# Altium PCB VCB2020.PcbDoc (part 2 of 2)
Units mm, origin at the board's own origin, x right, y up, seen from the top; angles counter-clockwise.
Board outline 146 x 101 mm, 2 copper layers (Top Layer, Bottom Layer); 144 components, 94 nets, 477 pads, 404 vias.
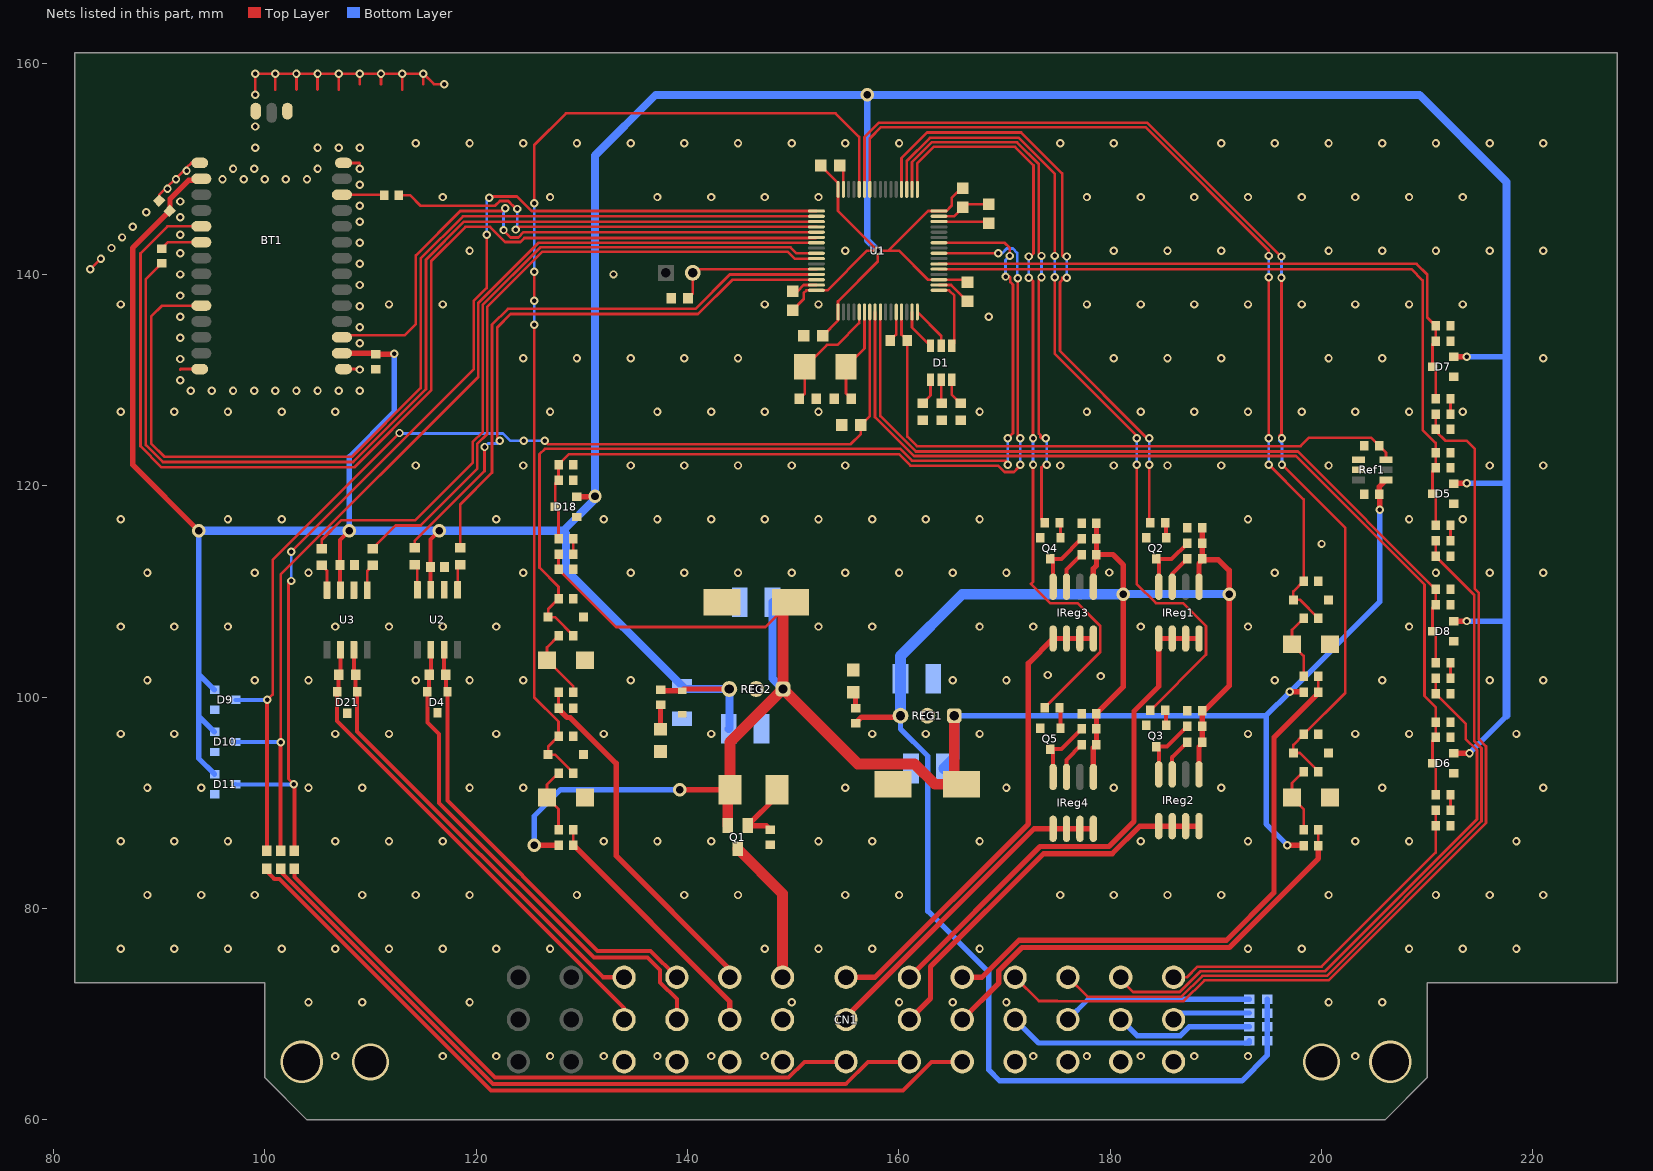
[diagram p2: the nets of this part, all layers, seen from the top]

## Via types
v1: diameter 0.787, hole 0.432, Top Layer to Bottom Layer, 391 vias
v2: diameter 1.27, hole 0.711, Top Layer to Bottom Layer, 9 vias
v3: diameter 3.5, hole 3, Top Layer to Bottom Layer, 2 vias
v4: diameter 4, hole 3.5, Top Layer to Bottom Layer, 2 vias

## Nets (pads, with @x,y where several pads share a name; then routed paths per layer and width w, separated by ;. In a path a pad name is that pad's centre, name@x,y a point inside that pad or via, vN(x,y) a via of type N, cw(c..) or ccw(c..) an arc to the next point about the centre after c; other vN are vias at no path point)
3v3: BT1.2 BT1.16 C5.2 C6.2 C7.2 C8.2 C9.2 C18.2 C19.2 C24.2 C28.2 C29.2 D3.1 D5.2 D6.2 D7.2 D8.2 D9.2 D10.2 D11.2 D18.2 R7.1 R8.2 REG2.3 U1.1 U1.19 U1.32 U1.48 U1.64 U2.3 U3.3 | length 440.5
  Top Layer w0.254: C9.2@149.946,136.6 151,137.654 151,138.25 151.25,138.5 U1.64@152.2,138.5 153.242,138.5 156.992,142.25 v1(158,142.25) ; C6.2@152.6,150.304 154.25,148.654 U1.48@154.25,148.05 154.25,146 v1(158,142.25) ; C5.2@152.8,134.196 154.25,135.646 U1.1@154.25,136.45 154.25,137.45 158,141.2 v1(158,142.25) ; C7.2@166.054,148.15 165.9,148.15 165,147.25 165,146.5 164.5,146 U1.32@163.8,146 162.758,146 159.008,142.25 ; C8.2@166.5,139.25 166.25,139.5 U1.19@163.8,139.5 162.758,139.5 160.008,142.25 159.008,142.25 ; v1(158,142.25) 159.008,142.25
  Top Layer w0.381: U3.3@107.165,110.134 107.125,110.174 C24.2@107.125,112.513 107.125,114.875 v2(108,115.75) ; U2.3@115.71,110.15 115.67,110.19 C19.2@115.67,112.329 115.67,114.92 v2(116.5,115.75)
  Top Layer w0.508: C28.2@90.995,146.005 91.038,146.048 91.038,147.145 92.792,148.9 93.85,148.9 BT1.2@94,149.05 ; C28.2@91,146 87.5,142.5 87.5,122 v2(93.75,115.75) ; BT1.16@107.3,132.55 110.4,132.55 C29.2@110.5,132.45 112.2,132.45 v1(112.25,132.5) ; D18.2@129.5,118.95 131.2,118.95 v2(131.25,119) ; R7.1@137.45,100.7 137.535,100.615 D3.1@139.5,100.615 139.655,100.77 REG2.3@143.96,100.77 ; D6.2@212.5,94.7 v1(214,94.7) ; D8.2@212.5,107.2 v1(213.75,107.2) ; D5.2@212.5,120.2 212.55,120.25 v1(213.75,120.25) ; D7.2@212.5,132.2 v1(213.75,132.2)
  Bottom Layer w0.508: v2(93.75,115.75) 93.75,102.2 ; D11.2@95.25,92.721 93.75,94.221 93.75,98.211 ; D10.2@95.25,96.711 93.75,98.211 ; D9.2@95.25,100.7 93.75,102.2 ; v2(108,115.75) 108,122.75 112.25,127 v1(112.25,132.5) ; v1(213.75,107.2) 217.45,107.2 217.5,107.25 ; v1(213.75,120.25) 217.25,120.25 217.5,120.5 ; v1(213.75,132.2) 217.45,132.2 217.5,132.25 ; v1(214,94.7) 217.5,98.2 217.5,98.25 ; 93.75,98.211 93.75,102.2
  Bottom Layer w0.635: v2(157,157) 157,143.25 v1(158,142.25)
  Bottom Layer w0.762: v2(93.75,115.75) v2(108,115.75) v2(116.5,115.75) 128.25,115.75 ; C18.2@143.9,97 143.96,97.06 REG2.3@143.96,100.77 ; REG2.3@144.23,100.77 REG2.3@143.96,100.77 ; 217.5,98.25 217.5,107.25 217.5,120.5 217.5,132.25 217.5,148.75 209.25,157 v2(157,157) 137,157 131.25,151.25 v2(131.25,119) 131.25,118.75 128.25,115.75 ; 128.25,115.75 128.5,115.5 128.5,112.05 R8.2@139.5,101.05 139.78,100.77 REG2.3@143.96,100.77
3v3ref: C3.2 C11.2 Ref1.6 U1.13 | length 59.3
  Top Layer w0.254: U1.13@160.25,136.45 160.25,134.3 C3.2@160.8,133.75 160.8,124.671 161.721,123.75 198,123.75 198.809,124.559 204.695,124.559 C11.2@205.45,123.804 206.1,123.154 Ref1.6@206.1,122.45
5v: C14.2 C34.2 C35.2 C36.2 C37.2 F1.1 F2.1 F3.1 F4.1 IReg1.1 IReg2.1 IReg3.1 IReg4.1 R6.1 R47.1 R48.1 R50.1 R51.1 R53.1 R54.1 R56.1 R57.1 REG1.3 | length 172.5
  Top Layer w0.508: R6.1@155.904,97.55 156.472,98.118 160.16,98.118 REG1.3@160.16,98.25 ; IReg4.1@178.405,92.45 178.405,95.205 R56.1@178.7,95.5 R57.1@178.7,97 C37.2@178.7,98.454 181.25,101.004 v2(181.25,109.75) 181.25,112.5 180.25,113.5 R53.1@178.7,113.5 ; IReg3.1@178.405,110.45 178.405,112.155 178.7,112.45 R53.1@178.7,113.5 ; C36.2@178.7,116.454 R54.1@178.7,115 R53.1@178.7,113.5 ; IReg2.1@188.405,92.95 188.405,95.309 188.7,95.604 188.7,97.059 R51.1@188.7,97.25 188.7,98.513 191.25,101.063 v2(191.25,109.75) 191.25,112 190.25,113 188.75,113 188.405,112.655 IReg1.1@188.405,110.45 ; R47.1@188.7,113.5 C34.2@188.7,116.013
  Bottom Layer w0.508: REG1.3@160.16,98.25 160.16,97.001 162.75,94.411 162.75,79.75 168.5,74 168.5,64.75 169.55,63.7 192.45,63.7 194.85,66.1 F4.1@194.85,67.5 F3.1@194.85,68.807 F1.1@194.85,70.113 F2.1@194.85,71.42
  Bottom Layer w0.762: v2(181.25,109.75) v2(191.25,109.75)
  Bottom Layer w1.016: REG1.3@160.16,98.25 160.16,101.74 C14.2@160.15,101.75 160.15,103.9 166,109.75 v2(181.25,109.75)
"APPS 1 5V": CN1.1 R16.1 R18.2 | length 33.7
  Top Layer w0.254: CN1.1@186,73.5 187.25,73.5 188.25,74.5 200,74.5 210.8,85.3 R18.2@210.8,87.837 R16.1@210.8,89.291
"APPS 1 Pwr": CN1.2 F1.2 | length 7.4
  Bottom Layer w0.508: CN1.2@186,69.5 186.613,70.113 F1.2@193.15,70.113
"APPS 2 5V": CN1.7 R12.1 R14.2 | length 75.1
  Top Layer w0.254: CN1.7@176,73.5 177.837,71.663 186.761,71.663 188.734,73.636 200.497,73.636 215.13,88.27 215.13,95.168 214.448,95.85 214.448,109.689 R14.2@210.8,113.337 R12.1@210.8,114.791
"APPS 2 Pwr": CN1.8 F2.2 | length 17.9
  Bottom Layer w0.508: CN1.8@176,69.5 177.92,71.42 F2.2@193.15,71.42
"Battery In": CN1.22 Q1.3 | length 13.9
  Top Layer w1.016: Q1.3@144.75,85.65 149,81.4 CN1.22@149,73.5
BOOT0: P1.2 R4.1 U1.60 | length 14.4
  Top Layer w0.254: R4.1@140.05,137.75 140.5,138.2 P1.2@140.5,140.149 140.851,140.5 U1.60@152.2,140.5
"BPPS 1 5V": CN1.4 R24.1 R26.2 | length 56.2
  Top Layer w0.254: CN1.4@181,73.5 181,73.25 182.155,72.095 186.582,72.095 188.555,74.068 200.318,74.068 214.699,88.448 214.699,94.989 213.636,96.051 213.636,97.501 R26.2@210.8,100.337 R24.1@210.8,101.791
"BPPS 1 Pwr": CN1.5 F3.2 | length 13.1
  Bottom Layer w0.508: CN1.5@181,69.5 182.532,67.968 186.634,67.968 187.473,68.807 F3.2@193.15,68.807
"BPPS 2 5V": CN1.10 R20.1 R22.2 | length 94.3
  Top Layer w0.254: CN1.10@171,73.5 173.25,71.25 175.007,71.25 175.025,71.232 186.94,71.232 188.913,73.205 200.676,73.205 215.562,88.091 215.562,95.347 214.88,96.029 214.88,109.868 214.5,110.248 214.5,123.5 213.75,124.25 211.75,124.25 210.8,125.2 R22.2@210.8,125.337 R20.1@210.8,126.791
"BPPS 2 Pwr": CN1.11 F4.2 | length 23.3
  Bottom Layer w0.508: CN1.11@171,69.5 173.218,67.282 193.15,67.282 F4.2@193.15,67.5
"BT NCTS": BT1.10 U1.50 | length 97.3
  Top Layer w0.254: BT1.10@94,137.05 90.3,137.05 89.25,136 89.25,124 90.5,122.75 108.25,122.75 114.75,129.25 114.75,141.5 118.75,145.5 126.25,145.5 U1.50@152.2,145.5
"BT NRTS": BT1.5 U1.54 | length 107.2
  Top Layer w0.254: BT1.5@94,144.55 90.8,144.55 88.25,142 88.25,123.75 90.25,121.75 108.471,121.75 115.75,129.029 115.75,141.25 119,144.5 121.312,144.5 122.744,143.068 124.179,143.068 124.565,143.455 152.155,143.455 U1.54@152.2,143.5
"BT Reset": BT1.17 U1.53 | length 56.6
  Top Layer w0.254: BT1.17@107.35,134 BT1.17@107.3,134.05 107.5,134.25 113.25,134.25 114.3,135.3 114.3,141.8 118.5,146 122.5,146 v1(122.75,146.25) ; v1(122.6,144.2) 122.6,144.15 123.25,143.5 124,143.5 124.5,144 U1.53@152.2,144
  Bottom Layer w0.254: v1(122.6,144.2) 122.6,146.1 v1(122.75,146.25)
"BT Rx": BT1.6 R33.2 | length 4
  Top Layer w0.254: R33.2@90.25,142.45 90.85,143.05 BT1.6@94,143.05
"BT Tx": BT1.26 R32.1 | length 4
  Top Layer w0.254: BT1.26@107.3,147.55 111.25,147.55 R32.1@111.3,147.5
"CAN Rx": R9.2 U1.62 | length 56.9
  Top Layer w0.254: R9.2@114.191,114.121 114.191,114.77 120.802,121.381 v1(120.802,123.672) ; v1(122.25,124.25) 122,124.5 122,135 123.25,136.25 141,136.25 144.25,139.5 U1.62@152.2,139.5
  Bottom Layer w0.254: v1(120.802,123.672) 121.129,124 122,124 v1(122.25,124.25)
"CAN Tx": R10.2 U1.61 | length 55
  Top Layer w0.254: R10.2@118.499,114.121 118.499,118.249 121.5,121.25 121.5,135.25 123,136.75 140.75,136.75 144,140 U1.61@152.2,140
CAN_N: CN1.29 D4.2 R11.1 U2.6 | length 47.9
  Top Layer w0.381: U2.6@115.71,104.5 115.71,102.286 R11.1@115.545,102.121 115.545,100.666 D4.2@115.395,100.516 115.395,97.605 116.5,96.5 116.5,90 131.135,75.365 136.237,75.365 137.4,74.202 137.4,73.024 139,71.424 CN1.29@139,69.5
CAN_P: CN1.28 D4.1 R11.2 U2.7 | length 43
  Top Layer w0.381: U2.7@116.98,104.5 116.98,102.286 R11.2@117.145,102.121 117.145,100.666 D4.1@117.295,100.516 117.295,90.205 131.5,76 136.5,76 CN1.28@139,73.5
"Dash Toggle": CN1.26 R59.1 R60.1 | length 24.1
  Top Layer w0.254: R59.1@129.2,86.008 R60.1@129.2,87.463
  Top Layer w0.508: R59.1@129.2,86.008 144,71.208 CN1.26@144,69.5
"Dash Toggle Interm": D20.2 R60.2 R61.1 | length 6.3
  Top Layer w0.254: R60.2@127.8,87.463 127.8,89.41 D20.2@126.71,90.5 126.71,91.722 R61.1@127.8,92.812
"Debug LED B": D1.6 U1.15 | length 3.9
  Top Layer w0.254: U1.15@161.25,136.45 161.25,135 D1.6@163,133.25
"Debug LED G": D1.5 U1.16 | length 4.1
  Top Layer w0.254: U1.16@161.75,136.45 164,134.2 D1.5@164,133.25
"Debug LED R": D1.4 U1.17 | length 6.5
  Top Layer w0.254: U1.17@163.8,138.5 164.75,138.5 165.25,138 165.25,133.5 D1.4@165,133.25
GND: BT1.1 BT1.14 BT1.15 BT1.28 BT1.29 BT1.31 C1.1 C2.1 C3.1 C4.1 C5.1 C6.1 C7.1 C8.1 C9.1 C10.1 C11.1 C12.2 C13.1 C14.1 C15.1 C16.2 C17.1 C18.1 C19.1 C20.1 C21.1 C22.1 C23.1 C24.1 C28.1 C29.1 C30.1 C31.1 C32.1 C33.1 C34.1 C35.1 C36.1 C37.1 C38.1 CN1.3 CN1.6 CN1.9 CN1.12 CN1.23 CN1.24 CN1.27 CN1.30 CN1.33 D3.2 D4.3 D5.1 D6.1 D7.1 D8.1 D9.1 D10.1 D11.1 D12.1 D13.1 D14.1 D15.1 D16.1 D17.1 D18.1 D19.1 D20.1 D21.3 DS1.2 DS2.2 Q2.2 Q3.2 Q4.2 Q5.2 R1.2 R2.2 R3.2 R4.2 R5.1 R8.1 R14.1 R15.1 R18.1 R19.1 R22.1 R23.1 R26.1 R27.1 R42.1 R45.1 R46.1 Ref1.1 Ref1.2 REG1.2 REG2.2 U1.12 U1.18 U1.31 U1.47 U1.63 U2.2 U3.2 | length 59.4
  Top Layer w0.254: v1(83.5,140.5) v1(84.5,141.5) ; C28.1@90.005,146.995 90.005,147.505 92.3,149.8 v1(92.6,149.8) 92.6,150.1 93.05,150.55 BT1.1@93.85,150.55 ; 92,131 92.05,131.05 BT1.14@93.85,131.05 ; v1(99.1,157) v1(99.1,159) v1(101,159) ; 101,157.5 v1(101,159) ; 103,157.5 v1(103,159) ; 105,157.5 v1(105,159) ; 107,157.5 v1(107,159) ; BT1.15@107.45,131.05 108.95,131.05 v1(109,131) ; BT1.28@107.45,150.55 108.95,150.55 109,150.5 ; 109,158 v1(109,159) ; 111,158 v1(111,159) ; 113,157.5 v1(113,159) ; 115,158 v1(115,159) ; v1(117,158) 116,158 v1(115,159) ; C9.1@149.946,138.4 150.4,138.4 151,139 U1.63@152.2,139 ; C6.1@154.4,150.304 154.75,149.954 U1.47@154.75,148.05 ; C3.1@159.2,133.75 159.75,134.3 U1.12@159.75,136.45 ; U1.18@163.8,139 164.95,139 C8.1@166.5,137.45 ; U1.31@163.8,145.5 165.204,145.5 C7.1@166.054,146.35 166.354,146.65 C2.1@168.5,146.65 ; v1(101,159) v1(103,159) ; v1(103,159) v1(105,159) ; v1(105,159) v1(107,159) ; v1(107,159) v1(109,159) ; v1(109,159) v1(111,159) ; v1(111,159) v1(113,159) ; v1(113,159) v1(115,159)
  other v1: 106.68,66.04 116.84,66.04 121.92,66.04 127,66.04 132.08,66.04 137.16,66.04 142.24,66.04 147.32,66.04 172.72,66.04 177.8,66.04 182.88,66.04 187.96,66.04 193.04,66.04 203.2,66.04 104.14,71.12 109.22,71.12 119.38,71.12 149.86,71.12 160.02,71.12 165.1,71.12 170.18,71.12 200.66,71.12 205.74,71.12 86.36,76.2 91.44,76.2 96.52,76.2 101.6,76.2 106.68,76.2 111.76,76.2 116.84,76.2 121.92,76.2 127,76.2 147.32,76.2 152.4,76.2 157.48,76.2 167.64,76.2 193.04,76.2 198.12,76.2 208.28,76.2 213.36,76.2 218.44,76.2 88.9,81.28 93.98,81.28 99.06,81.28 109.22,81.28 114.3,81.28 119.38,81.28 129.54,81.28 139.7,81.28 144.78,81.28 154.94,81.28 160.02,81.28 175.26,81.28 180.34,81.28 185.42,81.28 190.5,81.28 200.66,81.28 210.82,81.28 215.9,81.28 220.98,81.28 86.36,86.36 91.44,86.36 96.52,86.36 106.68,86.36 111.76,86.36 116.84,86.36 132.08,86.36 137.16,86.36 142.24,86.36 152.4,86.36 157.48,86.36 167.64,86.36 182.88,86.36 193.04,86.36 203.2,86.36 208.28,86.36 218.44,86.36 88.9,91.44 93.98,91.44 104.14,91.44 109.22,91.44 119.38,91.44 124.46,91.44 154.94,91.44 170.18,91.44 180.34,91.44 190.5,91.44 205.74,91.44 220.98,91.44 86.36,96.52 91.44,96.52 106.68,96.52 111.76,96.52 121.92,96.52 132.08,96.52 142.24,96.52 157.48,96.52 162.56,96.52 167.64,96.52 193.04,96.52 203.2,96.52 208.28,96.52 218.44,96.52 88.9,101.6 99.06,101.6 104.14,101.6 114.3,101.6 119.38,101.6 124.46,101.6 134.62,101.6 165.1,101.6 170.18,101.6 195.58,101.6 205.74,101.6 215.9,101.6 220.98,101.6 179.1,102 174.1,102.1 86.36,106.68 91.44,106.68 96.52,106.68 106.68,106.68 111.76,106.68 116.84,106.68 121.92,106.68 152.4,106.68 157.48,106.68 167.64,106.68 172.72,106.68 182.88,106.68 193.04,106.68 208.28,106.68 88.9,111.76 99.06,111.76 104.14,111.76 124.46,111.76 134.62,111.76 139.7,111.76 144.78,111.76 149.86,111.76 154.94,111.76 160.02,111.76 165.1,111.76 170.18,111.76 195.58,111.76 210.82,111.76 215.9,111.76 220.98,111.76 179.9,111.8 200,114.5 86.36,116.84 96.52,116.84 101.6,116.84 121.92,116.84 132.08,116.84 137.16,116.84 142.24,116.84 147.32,116.84 152.4,116.84 157.48,116.84 162.56,116.84 167.64,116.84 193.04,116.84 208.28,116.84 213.36,116.84 114.3,121.92 124.46,121.92 134.62,121.92 139.7,121.92 144.78,121.92 149.86,121.92 154.94,121.92 175.26,121.92 180.34,121.92 185.42,121.92 190.5,121.92 200.66,121.92 215.9,121.92 220.98,121.92 86.36,127 91.44,127 96.52,127 101.6,127 106.68,127 127,127 137.16,127 142.24,127 147.32,127 152.4,127 167.64,127 177.8,127 182.88,127 187.96,127 193.04,127 198.12,127 203.2,127 208.28,127 213.36,127 93,129 95,129 97,129 99,129 101,129 103,129 105,129 107,129 109,129 92,130 92,132 124.46,132.08 129.54,132.08 134.62,132.08 139.7,132.08 144.78,132.08 180.34,132.08 185.42,132.08 190.5,132.08 200.66,132.08 205.74,132.08 220.98,132.08 109,133.5 92,134 109,135 92,136 168.5,136 109,137 86.36,137.16 111.76,137.16 116.84,137.16 147.32,137.16 152.4,137.16 177.8,137.16 182.88,137.16 187.96,137.16 193.04,137.16 198.12,137.16 203.2,137.16 208.28,137.16 213.36,137.16 92,138 109,139 92,140 133,140 109,141 92,142 119.38,142.24 154.94,142.24 180.34,142.24 185.42,142.24 190.5,142.24 200.66,142.24 205.74,142.24 210.82,142.24 215.9,142.24 220.98,142.24 85.5,142.5 109,143 86.5,143.5 92,143.75 87.5,144.5 109,145 92,145.4 88.8,145.9 109,146.5 92,146.9 116.84,147.32 127,147.32 137.16,147.32 142.24,147.32 147.32,147.32 152.4,147.32 177.8,147.32 182.88,147.32 187.96,147.32 193.04,147.32 198.12,147.32 203.2,147.32 208.28,147.32 213.36,147.32 90.8,148.1 109,148.5 91.6,149 96,149 98,149 100,149 102,149 104,149 97,150 99,150 105,150 109,150 99.1,152 105,152 107,152 109,152 114.3,152.4 119.38,152.4 124.46,152.4 129.54,152.4 134.62,152.4 139.7,152.4 144.78,152.4 149.86,152.4 154.94,152.4 160.02,152.4 175.26,152.4 180.34,152.4 190.5,152.4 195.58,152.4 200.66,152.4 205.74,152.4 210.82,152.4 215.9,152.4 220.98,152.4 99.1,154
  other v3: 110,65.5 200,65.5
  other v4: 103.5,65.5 206.5,65.5
NetD1_1: D1.1 R3.1 | length 2.6
  Top Layer w0.254: R3.1@162.25,127.8 163,128.55 D1.1@163,130.05
NetD1_2: D1.2 R2.1 | length 2.3
  Top Layer w0.254: D1.2@164,130.05 164,127.854 R2.1@164.054,127.8
NetD1_3: D1.3 R1.1 | length 2.6
  Top Layer w0.254: D1.3@165,130.05 165,128.658 R1.1@165.859,127.8
NetD2_A: D2.A Q1.1 R5.2 | length 6.9
  Top Layer w0.508: R5.2@147.854,87.45 147.454,87.85 Q1.1@145.7,87.85 148.475,90.625 D2.A@148.475,91.25
NetDS1_1: DS1.1 R6.2 | length 1.6
  Top Layer w0.508: DS1.1@155.7,100.479 155.904,100.275 R6.2@155.904,98.95
NetDS2_1: DS2.1 R7.2 | length 2.3
  Top Layer w0.508: DS2.1@137.45,96.966 R7.2@137.45,99.3
NetIReg1_3: IReg1.3 R47.2 | length 3.2
  Top Layer w0.381: IReg1.3@185.865,110.45 185.865,111.669 R47.2@187.3,113.104
NetIReg1_4: IReg1.4 Q2.3 R48.2 | length 6.3
  Top Layer w0.381: IReg1.4@184.595,110.45 184.595,112.83 Q2.3@184.346,113.079 185.821,113.079 R48.2@187.3,114.559
NetIReg2_3: IReg2.3 R50.2 | length 3.6
  Top Layer w0.381: IReg2.3@185.865,92.7 185.865,94.315 R50.2@187.3,95.75
NetIReg2_4: IReg2.4 Q3.3 R51.2 | length 6.5
  Top Layer w0.381: IReg2.4@184.595,92.7 184.595,95.08 Q3.3@184.346,95.329 185.379,95.329 R51.2@187.3,97.25
NetIReg3_3: IReg3.3 R53.2 | length 3.6
  Top Layer w0.381: IReg3.3@175.865,110.45 175.865,112.065 R53.2@177.3,113.5
NetIReg3_4: IReg3.4 Q4.3 R54.2 | length 6.5
  Top Layer w0.381: IReg3.4@174.595,110.45 174.595,112.83 Q4.3@174.346,113.079 175.379,113.079 R54.2@177.3,115
NetIReg4_3: IReg4.3 R56.2 | length 3.6
  Top Layer w0.381: IReg4.3@175.865,92.45 175.865,94.065 R56.2@177.3,95.5
NetIReg4_4: IReg4.4 Q5.3 R57.2 | length 6.5
  Top Layer w0.381: IReg4.4@174.595,92.45 174.595,94.83 Q5.3@174.346,95.079 175.379,95.079 R57.2@177.3,97
NetQ2_1: Q2.1 R49.1 | length 1.5
  Top Layer w0.381: R49.1@185.2,116.509 185.296,116.413 Q2.1@185.296,115.079
NetQ3_1: Q3.1 R52.1 | length 1.5
  Top Layer w0.381: R52.1@185.2,98.759 185.296,98.663 Q3.1@185.296,97.329
NetQ4_1: Q4.1 R55.1 | length 1.5
  Top Layer w0.254: R55.1@175.2,116.509 175.296,116.413 Q4.1@175.296,115.079
NetQ5_1: Q5.1 R58.1 | length 2
  Top Layer w0.381: R58.1@175.2,99 175.296,98.904 Q5.1@175.296,97.079
NetR9_1: R9.1 U2.4 | length 2.5
  Top Layer w0.254: R9.1@114.191,112.521 114.44,112.271 U2.4@114.44,110.15
NetR10_1: R10.1 U2.1 | length 2.5
  Top Layer w0.254: U2.1@118.25,110.15 118.25,112.272 R10.1@118.499,112.521
NetR12_2: R12.2 R13.1 | length 1.5
  Top Layer w0.254: R12.2@212.2,114.791 R13.1@212.2,116.246
NetR16_2: R16.2 R17.1 | length 1.5
  Top Layer w0.254: R16.2@212.2,89.291 R17.1@212.2,90.746
NetR20_2: R20.2 R21.1 | length 1.5
  Top Layer w0.254: R20.2@212.2,126.791 R21.1@212.2,128.246
NetR24_2: R24.2 R25.1 | length 1.5
  Top Layer w0.254: R24.2@212.2,101.791 R25.1@212.2,103.246
NetR28_1: R28.1 U3.4 | length 2.5
  Top Layer w0.254: R28.1@105.396,112.463 105.895,111.964 U3.4@105.895,110.134
NetR29_1: R29.1 U3.1 | length 2.5
  Top Layer w0.254: U3.1@109.705,110.134 109.705,111.964 R29.1@110.204,112.463
NetR43_2: R43.2 R44.1 | length 1.5
  Top Layer w0.254: R43.2@129.2,113.541 R44.1@129.2,114.996
NRST: C1.2 D9.3 F5.1 U1.7 | length 104.1
  Top Layer w0.254: v1@100.193,99.693 v1(100.25,99.75) 100.75,100.25 100.75,113 v1(112.75,125) ; v1(126.5,124.25) 126.818,123.932 155.432,123.932 156.4,124.9 C1.2@156.4,125.75 157.25,126.6 U1.7@157.25,136.45
  Top Layer w0.381: F5.1@100.193,85.45 v1@100.193,99.693
  Bottom Layer w0.254: v1(112.75,125) 112.801,124.948 122.539,124.948 123.237,124.25 v1(124.5,124.25) ; v1(124.5,124.25) v1(126.5,124.25)
  Bottom Layer w0.381: D9.3@97.25,99.75 v1(100.25,99.75)
"NRST F": CN1.15 F5.2 | length 75.7
  Top Layer w0.381: F5.2@100.193,83.75 100.193,83.507 100.9,82.8 101.4,82.8 121.4,62.8 160.376,62.8 163.076,65.5 CN1.15@166,65.5
"Ph0 OSC In": C4.2 U1.5 X1.2 | length 11.1
  Top Layer w0.254: C4.2@150.596,128.25 151.1,128.754 X1.2@151.1,131.25 153.191,133.341 154.183,133.341 156.25,135.408 U1.5@156.25,136.45
"Ph1 OSC Out": C10.2 U1.6 X1.1 | length 9.1
  Top Layer w0.254: C10.2@155.5,128.25 155,128.75 X1.1@155,131.25 156.75,133 U1.6@156.75,136.45
"RTD BTN": CN1.14 R34.1 R35.1 | length 43.4
  Top Layer w0.254: R34.1@199.7,85.963 R35.1@199.7,87.463
  Top Layer w0.508: CN1.14@166,69.5 169.468,72.968 169.468,74.134 171.648,76.314 191.284,76.314 199.7,84.73 R34.1@199.7,85.963
"RTD LED 1": R52.2 U1.35 | length 79.8
  Top Layer w0.254: U1.35@160.75,148.05 160.75,150.75 162.932,152.932 171.358,152.932 174.75,149.54 v1(174.75,141.75) ; v1(174.75,139.75) 174.75,132.5 182.5,124.75 v1(182.5,124.5) ; v1(182.5,122) 182.5,110.719 184.324,108.895 186.886,108.895 189.06,106.721 189.06,104.018 R52.2@183.8,98.759
  Bottom Layer w0.254: v1@174.5,141.75 174.75,141.499 v1(174.75,139.75) ; v1@174.5,141.75 v1(174.75,141.75) ; v1(182.5,122) v1(182.5,124.5)
"RTD LED 2": R58.2 U1.33 | length 73.4
  Top Layer w0.254: U1.33@161.75,148.05 161.75,150.529 163.29,152.068 171,152.068 172.75,150.318 172.75,142 172.45,141.7 v1(172.3,141.7) ; v1(172.3,139.7) 172.368,139.7 172.7,139.368 v1(172.7,124.5) ; v1(172.7,122) 172.691,121.991 172.691,110.911 172.5,110.719 174.324,108.895 176.886,108.895 179.06,106.721 179.06,104.26 R58.2@173.8,99
  Bottom Layer w0.254: v1(172.3,139.7) v1(172.3,141.7) ; v1@172.5,124.5 172.7,124.299 v1(172.7,122) ; v1@172.5,124.5 v1(172.7,124.5)
"RTD LED Output 1": CN1.17 IReg2.5 IReg2.6 IReg2.7 IReg2.8 | length 36.7
  Top Layer w0.508: CN1.17@161,69.5 163,71.5 163,74.5 173.682,85.182 180.182,85.182 182.8,87.8 IReg2.5@184.595,87.8 IReg2.6@185.865,87.8 IReg2.7@187.135,87.8 IReg2.8@188.405,87.8
"RTD LED Output 2": CN1.20 IReg4.5 IReg4.6 IReg4.7 IReg4.8 | length 31
  Top Layer w0.508: CN1.20@155,69.5 155,69.75 172.8,87.55 IReg4.5@174.595,87.55 IReg4.6@175.865,87.55 IReg4.7@177.135,87.55 IReg4.8@178.405,87.55
RTD_BTN_Interm: D13.2 R35.2 R36.1 | length 6.4
  Top Layer w0.254: R35.2@198.3,87.463 198.3,89.41 D13.2@197.21,90.5 197.21,91.873 R36.1@198.3,92.963
"Sensor CAN Rx": R28.2 U1.57 | length 67.5
  Top Layer w0.254: R28.2@105.396,114.063 105.396,114.896 107.25,116.75 114.25,116.75 119.671,122.171 119.671,124.14 120.636,125.106 120.636,137.136 126.068,142.568 149.75,142.568 150.318,142 U1.57@152.2,142
"Sensor CAN Tx": R29.2 U1.58 | length 62.3
  Top Layer w0.254: R29.2@110.204,114.063 112.391,116.25 114.75,116.25 120.103,121.603 120.103,123.962 121.068,124.927 121.068,136.958 126.247,142.136 149.5,142.136 150.136,141.5 U1.58@152.2,141.5
Sensor_CAN_N: CN1.32 D21.2 R30.1 U3.6 | length 46.4
  Top Layer w0.381: U3.6@107.165,104.484 107.165,102.269 R30.1@107,102.104 107,100.65 D21.2@106.85,100.5 106.85,97.726 134,70.576 CN1.32@134,69.5
Sensor_CAN_P: CN1.31 D21.1 R30.2 U3.7 | length 42.7
  Top Layer w0.381: U3.7@108.435,104.484 108.435,102.269 R30.2@108.6,102.104 108.6,100.65 D21.1@108.75,100.5 108.75,96.75 132,73.5 CN1.31@134,73.5
"Shutdown Tap Interm": D17.2 R40.1 R41.2 | length 6.8
  Top Layer w0.254: R41.2@127.8,105.812 126.71,104.722 D17.2@126.71,103.5 129.2,101.01 R40.1@129.2,100.463
Shutdown_Tap: CN1.25 R40.2 R42.2 | length 33.8
  Top Layer w0.254: R42.2@127.8,98.963 R40.2@127.8,100.463
  Top Layer w0.508: R42.2@127.8,98.963 127.8,98.902 128.621,98.081 128.9,98.081 133.25,93.731 133.25,85 144,74.25 CN1.25@144,73.5
"TSA BTN": CN1.13 R37.1 R38.1 | length 55
  Top Layer w0.254: R37.1@199.7,100.463 R38.1@199.7,101.963
  Top Layer w0.508: CN1.13@166,73.5 167.864,73.5 171.364,77 191,77 195.5,81.5 195.5,96.202 199.7,100.402 R37.1@199.7,100.463
"TSA LED 1": R49.2 U1.36 | length 59.1
  Top Layer w0.254: U1.36@160.25,148.05 160.25,151 162.682,153.432 171.568,153.432 175.449,149.551 175.449,141.801 175.55,141.7 v1(175.9,141.7) ; v1(175.9,139.7) 175.45,139.7 175.449,139.699 175.449,139.461 175.25,139.262 175.25,132.75 183.5,124.5 v1(183.7,124.5) ; v1(183.7,122) 183.7,117.009 183.5,116.809 R49.2@183.8,116.509
  Bottom Layer w0.254: v1(175.9,139.7) 175.9,141.349 175.549,141.7 v1(175.9,141.7) ; v1(183.7,122) v1(183.7,124.5)
"TSA LED 2": R55.2 U1.34 | length 51.4
  Top Layer w0.254: U1.34@161.25,148.05 161.25,150.639 163.111,152.5 171.179,152.5 173.25,150.429 173.25,141.999 v1(173.5,141.75) ; v1(173.5,139.75) 173.25,139.5 173.25,124.938 173.399,124.789 173.399,124.601 173.499,124.5 v1(173.9,124.5) ; R55.2@173.8,116.509 173.5,116.808 173.5,121.75 173.75,122 v1(174,122)
  Bottom Layer w0.254: v1(173.5,139.75) v1(173.5,141.75) ; v1(173.9,124.5) 174,124.4 v1(174,122)
"TSA LED Output 1": CN1.16 IReg1.5 IReg1.6 IReg1.7 IReg1.8 | length 49.4
  Top Layer w0.508: CN1.16@161,73.5 173.368,85.868 179.868,85.868 182.25,88.25 182.25,98.669 184.595,101.014 IReg1.5@184.595,105.55 IReg1.6@185.865,105.55 IReg1.7@187.135,105.55 IReg1.8@188.405,105.55
"TSA LED Output 2": CN1.19 IReg3.5 IReg3.6 IReg3.7 IReg3.8 | length 45.6
  Top Layer w0.508: CN1.19@155,73.5 157.75,73.5 172.25,88 172.25,103.205 IReg3.5@174.595,105.55 IReg3.6@175.865,105.55 IReg3.7@177.135,105.55 IReg3.8@178.405,105.55
TSA_BTN_Interm: D15.2 R38.2 R39.1 | length 6.4
  Top Layer w0.254: R38.2@198.3,101.963 198.3,103.91 D15.2@197.21,105 197.21,106.373 R39.1@198.3,107.463
"UC APPS 1": C21.2 D6.3 R17.2 R19.2 U1.8 | length 89.1
  Top Layer w0.254: U1.8@157.75,136.45 157.75,126.5 161.432,122.818 197.575,122.818 209.745,110.648 209.745,100.111 210.8,99.056 C21.2@210.8,97.644 R19.2@210.8,96.189 210.5,95.889 D6.3@210.5,93.75 210.8,93.45 R17.2@210.8,90.746
"UC APPS 2": C20.2 D5.3 R13.2 R15.2 U1.21 | length 70.2
  Top Layer w0.254: U1.21@163.8,140.5 208.5,140.5 209.568,139.432 209.568,125.288 210.8,124.056 C20.2@210.8,123.144 R15.2@210.8,121.689 210.5,121.389 D5.3@210.5,119.25 210.8,118.95 R13.2@210.8,116.246
"UC BPPS 1": C23.2 D8.3 R25.2 R27.2 U1.9 | length 76.4
  Top Layer w0.254: U1.9@158.25,136.45 158.25,126.611 161.611,123.25 197.754,123.25 C23.2@210.8,110.204 R27.2@210.8,108.75 210.5,108.45 D8.3@210.5,106.25 210.8,105.95 R25.2@210.8,103.246
"UC BPPS 2": C22.2 D7.3 R21.2 R23.2 U1.22 | length 58.9
  Top Layer w0.254: U1.22@163.8,141 209,141 210,140 210,137.5 210,135.944 C22.2@210.8,135.144 R23.2@210.8,133.689 210.5,133.389 D7.3@210.5,131.25 210.8,130.95 R21.2@210.8,128.246
"UC BT Rx": R32.2 U1.52 | length 42.6
  Top Layer w0.254: R32.2@112.7,147.5 113.75,147.5 114.75,146.5 121.8,146.5 ; 121.8,146.5 122.248,146.948 123.039,146.948 123.449,146.539 ; 123.488,146.5 123.788,146.2 v1(123.9,146.2) ; v1(123.75,144.25) 124,144.5 U1.52@152.2,144.5
  Bottom Layer w0.254: v1(123.75,144.25) 123.9,144.4 v1(123.9,146.2)
"UC BT Tx": R33.1 U1.51 | length 98.5
  Top Layer w0.254: R33.1@90.25,141.05 88.75,139.55 88.75,123.861 90.361,122.25 108.361,122.25 115.25,129.139 115.25,141.389 118.861,145 U1.51@152.2,145
"UC Dash Toggle": C38.2 D19.2 R61.2 U1.44 | length 100
  Top Layer w0.254: v1(125.5,135.25) 125.5,99.982 127.8,97.682 C38.2@127.8,96.321 126.825,95.346 D19.2@126.825,94.567 127.446,94.567 R61.2@129.2,92.812 ; v1(125.5,137.5) v1(125.5,140.25) ; v1(125.5,146.75) 125.5,152.25 128.5,155.25 154,155.25 156.25,153 U1.44@156.25,148.05
  Bottom Layer w0.254: v1(125.5,135.25) v1(125.5,137.5) ; v1(125.5,140.25) v1(125.5,146.75)
"UC RTD BTN": C30.2 D12.2 R36.2 U1.43 | length 105.2
  Top Layer w0.254: U1.43@156.75,148.05 156.75,153 158.114,154.364 183.497,154.364 196.161,141.7 v1(196.2,141.7) ; v1(196.2,139.7) 196.2,124.95 196,124.75 v1(196.25,124.5) ; v1(196.25,122) 202.25,116 202.25,100.421 C30.2@198.3,96.471 197.325,95.496 D12.2@197.325,94.717 197.946,94.717 R36.2@199.7,92.963
  Bottom Layer w0.254: v1(196.2,139.7) v1(196.2,141.7) ; v1(196.25,122) 196.25,123.999 196,124.249 v1@196.25,124.499
"UC Shutdown Tap": C32.2 D16.2 R41.1 U1.26 | length 93.2
  Top Layer w0.254: R41.1@129.2,105.812 127.446,107.567 D16.2@126.825,107.567 126.825,108.346 C32.2@127.8,109.321 127.8,110.45 126,112.25 126,123 126.5,123.5 160.139,123.5 161.253,122.386 170.114,122.386 170.3,122.2 v1(170.3,122) ; U1.26@163.8,143 170,143 170.5,142.5 v1(170.5,141.75) ; v1(170.1,139.8) 170.45,139.8 170.552,139.698 170.552,139.274 170.8,139.026 170.8,124.982 170.318,124.5 v1(170.3,124.5)
  Bottom Layer w0.254: v1(170.1,139.8) 170.1,141.35 v1(170.5,141.75) ; v1(170.3,122) v1(170.3,124.5)
"UC SWCLK": D11.3 F7.1 U1.49 | length 107
  Top Layer w0.254: v1(102.5,113.75) 119.773,131.023 119.773,137.494 121,138.721 v1(121,143.75) ; v1(102.5,111) 102.25,110.75 102.25,92.25 v1(102.75,91.75) ; v1(121.25,147.25) 121.38,147.38 123.87,147.38 125.25,146 U1.49@152.2,146
  Top Layer w0.381: v1(102.75,91.75) 102.807,91.693 F7.1@102.807,85.45
  Bottom Layer w0.254: v1(102.5,111) v1(102.5,113.75) ; v1(121,143.75) 121,147 v1(121.25,147.25)
  Bottom Layer w0.381: D11.3@97.25,91.771 97.271,91.75 v1(102.75,91.75)
"UC SWCLK F": CN1.21 F7.2 | length 61.4
  Top Layer w0.381: F7.2@102.807,83.75 102.807,82.993 121.8,64 149.576,64 151.076,65.5 CN1.21@155,65.5
"UC SWO": D10.3 F6.1 U1.55 | length 98.2
  Top Layer w0.254: v1(101.5,95.75) 101.5,111.611 120.205,130.315 120.205,137.315 125.889,143 126.5,143 U1.55@152.2,143
  Top Layer w0.381: F6.1@101.5,85.45 v1(101.5,95.75)
  Bottom Layer w0.381: D10.3@97.25,95.761 101.489,95.761 v1(101.5,95.75)
"UC SWO F": CN1.18 F6.2 | length 68.9
  Top Layer w0.381: F6.2@101.5,83.75 101.5,83.51 121.61,63.4 154.976,63.4 157.076,65.5 CN1.18@161,65.5
"UC TSA BTN": C31.2 D14.2 R39.2 U1.42 | length 85.8
  Top Layer w0.254: U1.42@157.25,148.05 157.25,152.889 158.292,153.932 183.318,153.932 195,142.25 v1(195,141.75) ; v1(195,122) 198.3,118.7 C31.2@198.3,110.971 197.325,109.996 D14.2@197.325,109.217 197.946,109.217 R39.2@199.7,107.463 ; v1(195,124.5) v1(195,139.75)
  Bottom Layer w0.254: v1(195,122) v1(195,124.5) ; v1(195,139.75) v1(195,141.75)
"UC Vbatt": C33.2 D18.3 R44.2 R45.2 U1.24 | length 79.9
  Top Layer w0.254: R44.2@127.8,114.996 127.8,117.7 D18.3@127.5,118 127.5,120.241 R45.2@127.8,120.541 C33.2@127.8,121.996 128.804,123 160,123 161.089,121.911 169.402,121.911 170.011,121.301 170.88,121.301 v1@171.289,121.711 ; U1.24@163.8,142 v1(169.4,142) ; v1(171.25,139.65) 171.25,124.75 v1(171.5,124.5)
  Bottom Layer w0.254: v1(169.4,142) 169.762,142 170.211,142.449 170.789,142.449 171.198,142.039 171.198,139.702 v1(171.25,139.65) ; v1(171.5,122) v1(171.5,124.5)
Vbatt: C12.1 C13.2 C15.2 C16.1 C17.2 D2.K Q1.2 R34.2 R37.2 R43.1 R46.2 R59.2 Ref1.4 REG1.1 REG2.1 | length 186.9
  Top Layer w0.254: R43.1@127.8,113.541 R46.2@127.8,112.087 133.25,106.637 147.387,106.637 C16.1@149.04,108.29
  Top Layer w0.508: v2(125.5,86) 127.792,86 R59.2@127.8,86.008 ; v2(139.25,91.25) D2.K@144.025,91.25 ; v1(196.75,86) 198.263,86 R34.2@198.3,85.963 ; v1(197,100.5) 198.263,100.5 R37.2@198.3,100.463 ; v1(205.5,117.75) 205.5,119.146 C15.2@205.45,119.196 205.45,119.9 Ref1.4@206.1,120.55
  Top Layer w1.016: Q1.2@143.8,87.85 143.8,91.025 D2.K@144.025,91.25 144.025,95.755 REG2.1@149.04,100.77 ; C16.1@149.04,108.29 REG2.1@149.04,100.77 ; REG1.1@165.24,98.25 165.24,92.46 C12.1@165.95,91.75 163.42,91.75 161.484,93.686 156.124,93.686 REG2.1@149.04,100.77
  Bottom Layer w0.508: v2(125.5,86) 125.5,88.75 128,91.25 v2(139.25,91.25) ; REG1.1@165.24,98.25 194.75,98.25 ; v1(196.75,86) 194.75,88 194.75,98.25 ; v1(205.5,117.75) 205.5,109 v1(197,100.5) 194.75,98.25
  Bottom Layer w0.762: C17.2@148.05,109 148.05,101.76 REG2.1@149.04,100.77
  Bottom Layer w1.016: C13.2@164.25,93.25 165.24,94.24 REG1.1@165.24,98.25
Vcap: C2.2 U1.30 | length 4.8
  Top Layer w0.254: U1.30@163.8,145 168.35,145 C2.2@168.5,144.85
pads on no net: BT1.3 BT1.4 BT1.7 BT1.8 BT1.9 BT1.11 BT1.12 BT1.13 BT1.18 BT1.19 BT1.20 BT1.21 BT1.22 BT1.23 BT1.24 BT1.25 BT1.27 BT1.30 CN1.34 CN1.35 CN1.36 CN1.37 CN1.38 CN1.39 IReg1.2 IReg2.2 IReg3.2 IReg4.2 P1.1 Ref1.3 Ref1.5 U1.2 U1.3 U1.4 U1.10 U1.11 U1.14 U1.20 U1.23 U1.25 U1.27 U1.28 U1.29 U1.37 U1.38 U1.39 U1.40 U1.41 U1.45 U1.46 U1.56 U1.59 U2.5 U2.8 U3.5 U3.8

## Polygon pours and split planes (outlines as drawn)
GND on Top Layer "Top Layer-No Net" (solid, pour order 4): 84,159 84,75 102,75 102,64 104,62 206,62 208,64 208,75 226,75 226,159
GND on Bottom Layer "Bottom Layer-GND" (solid, pour order 6): 84,159 84,75 102,75 102,64 104,62 206,62 208,64 208,75 226,75 226,159

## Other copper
Multi-Layer:
  pour cut-out: 108.5,129.5 92.5,129.5 92.5,150.5 82,140 82,161 98.5,161 98.5,150.5 95.5,150.5 95.5,148.5 105.5,148.5 105.5,151.5 108.5,151.5

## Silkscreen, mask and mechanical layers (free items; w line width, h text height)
Top Overlay:
  text "37" at 124,76 h1
  text "4" at 181,76 h1
  text "1" at 186,76 h1
Board Outline:
  lines w0.254: 82,161 82,73 100,73 100,64 104,60 206,60 210,64 210,73 228,73 228,161 ; 82,161 82,161 ; 82,161 228,161 ; 228,161 228,161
